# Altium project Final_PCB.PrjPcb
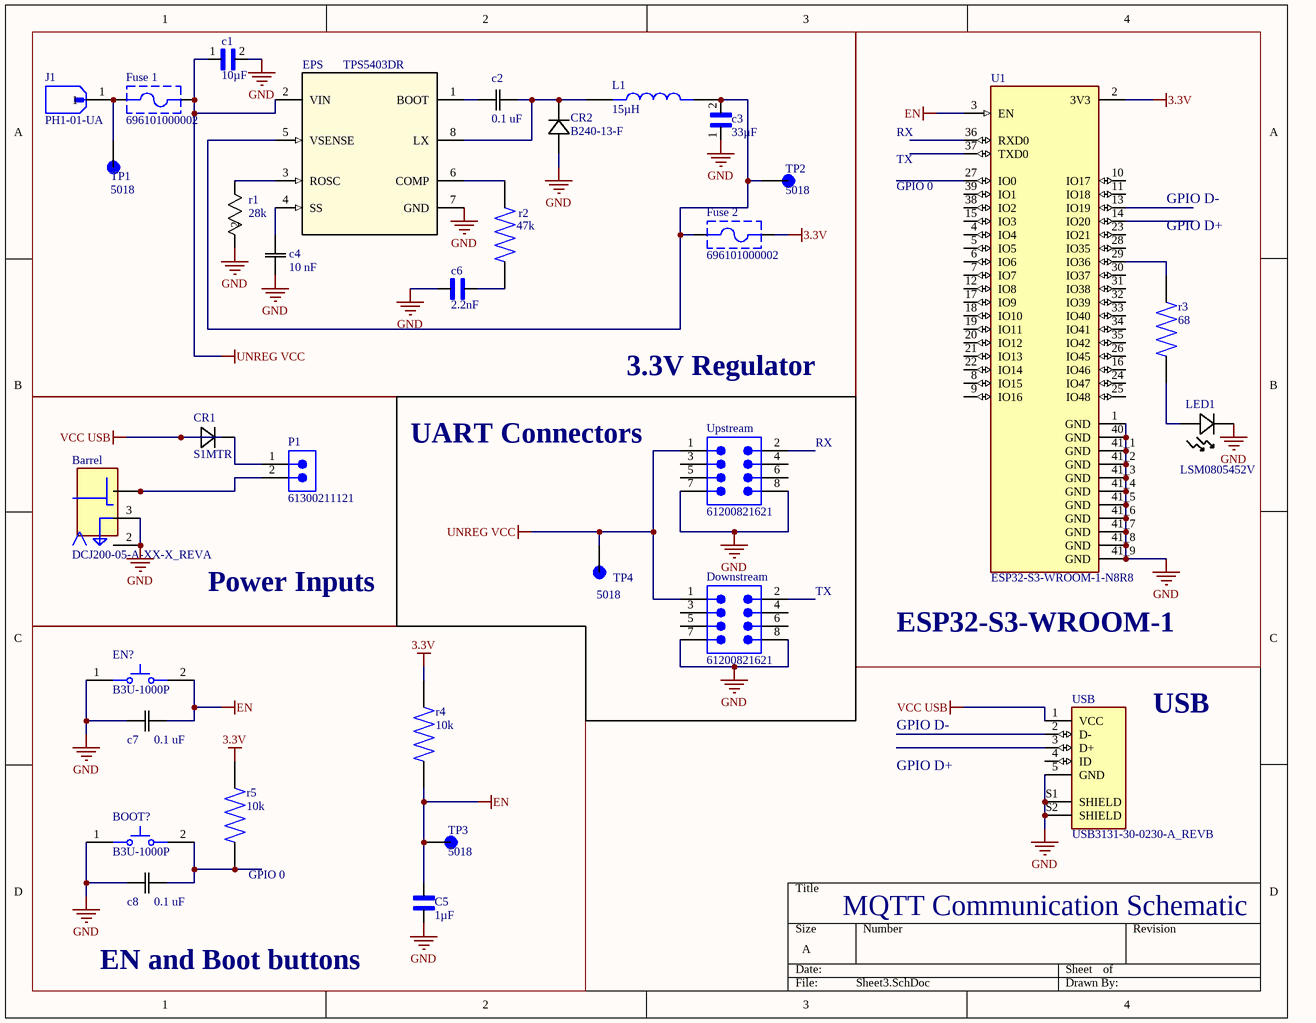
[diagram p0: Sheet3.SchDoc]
1 sheet, 33 parts. Net scope: global (net labels, ports and power ports of the same name join across sheets).
Board file: PCB3.PcbDoc

## Sheet Sheet3.SchDoc
size A; SheetNumber: 1; SheetTotal: 1

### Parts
Barrel  DCJ200-05-A-XX-X_REVA  [GCT_DCJ200-05-A-XX-X_REVA]
BOOT?  B3U-1000P  [OMRON-B3U-1000_V]
c1  value 10µF  [CAPC3216X190N]  (hidden comment: GRJ31CR61E106KE11L)
c2  0.1 uF  [CAP_KGM21_KAV]
c3  value 33µF  [CAPC3216X180N]  (hidden comment: C3216X7S0J336M160AC)
c4  10 nF  [CAP_X7R_0805_AVX]
C5  value 1µF  [CAPC2012X140N]  (hidden comment: CL21B105KBFNNNE)
c6  value 2.2nF  [CAPC3216X130N]  (hidden comment: C3216C0G2J222J115AA)
c7  0.1 uF  [CAP_KGM21_KAV]
c8  0.1 uF  [CAP_KGM21_KAV]
CR1  S1MTR  [SMA_SDS]
CR2  B240-13-F  [SMB_DIO]
Downstream  61200821621  [61200821621]
EN?  B3U-1000P  [OMRON-B3U-1000_V]
EPS  TPS5403DR  [D0008A_N]
Fuse_1  696101000002  [696101000002]
Fuse_2  696101000002  [696101000002]
J1  PH1-01-UA  [ADAM-TECH_PH1-01-UA]
L1  value 15µH  [INDC2012X145N]  (hidden comment: MLF2012C820MT000)
LED1  LSM0805452V  [LED_05452V_VCC]
P1  61300211121  [61300211121]
r1  28k  [RC1206N_YAG]
r2  value 47k  [RESC3116X65N]  (hidden comment: RC1206FR-1047KL)
r3  value 68  [RESC3216X55N]  (hidden comment: HRG3216P-68R0-D-T1)
r4  value 10k  [RESC2012X65N]  (hidden comment: RMCF0805FT10K0)
r5  value 10k  [RESC2012X65N]  (hidden comment: RMCF0805FT10K0)
TP1  5018  [TP470X343]
TP2  5018  [TP470X343]
TP3  5018  [TP470X343]
TP4  5018  [TP470X343]
U1  ESP32-S3-WROOM-1-N8R8  [XCVR_ESP32S3WROOM1N8R8]
Upstream  61200821621  [61200821621]
USB  USB3131-30-0230-A_REVB  [GCT_USB3131-30-0230-A_REVB]

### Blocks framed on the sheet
3.3V Regulator: c1-c4 c6 CR2 EPS Fuse_1 Fuse_2 J1 L1 r1 r2 TP1 TP2
ESP32-S3-WROOM-1: LED1 r3 U1
Power Inputs: Barrel CR1 P1
EN and Boot buttons: BOOT? C5 c7 c8 EN? r4 r5 TP3

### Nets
3.3V: Fuse_2.2 r4.2 r5.2 U1.2(3V3)
EN: C5.1 c7.2 EN?.2 r4.1 TP3.TP U1.3(EN)
GND: Barrel.2 Barrel.3 BOOT?.1 c1.2 c3.1 c4.1 C5.2 c6.1 c7.1 c8.1 CR2.2 Downstream.7 Downstream.8 EN?.1 EPS.7(GND) LED1.2 r1.2 U1.1(GND) U1.40(GND) U1.41_1(GND) U1.41_2(GND) U1.41_3(GND) U1.41_4(GND) U1.41_5(GND) U1.41_6(GND) U1.41_7(GND) U1.41_8(GND) U1.41_9(GND) Upstream.7 Upstream.8 USB.5(GND) USB.S1(SHIELD) USB.S2(SHIELD)
UNREG VCC: c1.1 Downstream.1 EPS.2(VIN) Fuse_1.2 TP4.TP Upstream.1
VCC USB: CR1.2 USB.1(VCC)
NetBarrel_1.1: Barrel.1.1 Barrel.1.2 P1.2
NetBOOT?_2: BOOT?.2 c8.2 r5.1
Netc2_1: c2.1 EPS.1(BOOT)
Netc2_2: c2.2 CR2.1 EPS.8(LX) L1.1
Netc3_2: c3.2 EPS.5(VSENSE) Fuse_2.1 L1.2 TP2.TP
Netc4_2: c4.2 EPS.4(SS)
Netc6_2: c6.2 r2.1
NetCR1_1: CR1.1 P1.1
NetEPS_3: EPS.3(ROSC) r1.1
NetEPS_6: EPS.6(COMP) r2.2
NetFuse_1_1: Fuse_1.1 J1.1 TP1.TP
NetLED1_1: LED1.1 r3.1
Netr3_2: r3.2 U1.29(IO36)

Not connected (* = marked no-connect by the designer): Downstream 2 3 4 5 6; U1 4(IO4) 5(IO5) 6(IO6) 7(IO7) 8(IO15) 9(IO16) 10(IO17) 11(IO18) 12(IO8) 13(IO19) 14(IO20) 15(IO3) 16(IO46) 17(IO9) 18(IO10) 19(IO11) 20(IO12) 21(IO13) 22(IO14) 23(IO21) 24(IO47) 25(IO48) 26(IO45) 27(IO0) 28(IO35) 30(IO37) 31(IO38) 32(IO39) 33(IO40) 34(IO41) 35(IO42) 36(RXD0) 37(TXD0) 38(IO2) 39(IO1); Upstream 2 3 4 5 6; USB 2(D-) 3(D+) 4(ID)

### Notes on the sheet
- RX
- TX
- GPIO 0
- GPIO D+
- GPIO D-
- UART Connectors
- USB
- (near r5) GPIO 0
- MQTT Communication Schematic

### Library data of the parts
Barrel = CMP-002-00092-1: Power Barrel Connector Jack 2.05mm ID (0.081), 5.50mm OD (0.217) Surface Mount, Right Angle; MF: Global Connector Technology; MP: DCJ200-05-A-K1-A
BOOT? EN? = CMP-011-00000-2: Tactile Switch, SPST-NO, 0.05 A, 12 V, -25 to 70 degC, 2-Pin SMD, RoHS, Tape and Reel; Manufacturer: Omron Electronic Components; IP Rating: IP40; Current Rating: 50mA; Max Contact Resistance: 100mohm; Operating Force: 153gf; Throw Configuration: SPST; Resistance: 0.1Ohm; Max Voltage Rating (DC): 12V
c1 = CMP-001-00086-1: CAP CER 10UF 25V X5R 1206
c2 c7 c8 = CMP-001-00087-1: No Description Available; Mfr_Name: KYOCERA AVX; Type: Ceramic Capacitors
c3 = CMP-001-00088-1: 33 ÂµF Â±20% 6.3V Ceramic Capacitor X7S 1206 (3216 Metric); MF: TDK
c4 = CMP-001-00083-1: No Description Available; Mfr_Name: KYOCERA AVX
C5 = CMP-001-00089-1: 1 ÂµF Â±10% 50V Ceramic Capacitor X7R 0805 (2012 Metric); MF: Samsung Electro-Mechanics
c6 = CMP-001-00085-1: 2200 pF Â±5% 630V Ceramic Capacitor C0G, NP0 1206 (3216 Metric); MF: TDK
CR1 = CMP-084-000000-1: No Description Available; Mfr_Name: SMC Diode Solutions
CR2 = CMP-047-000000-1: No Description Available; Mfr_Name: Diodes Inc
Downstream Upstream = CMP-002-00099-1: WR-BHD Male Box Header, THT Straight, pitch 2.54mm, 2 row, 8 pin; Manufacturer: Wurth Elektronik; Working Voltage: 250V; Insulation Resistance: 1000MOhm; Contact Resistance: 20mOhm; Rated Current: 3A; Withstanding Voltage: 500V
EPS = CMP-011-000000-1: No Description Available; Mfr_Name: Texas Instruments
Fuse_1 Fuse_2 = CMP-040-000000-1: WR-FSH Fuseholder THT Blocks PCB Clip Cover; Manufacturer: Wurth Elektronik; Fuse Size: 5x20mm
J1 = CMP-002-00312-1: Pin Header 1P .100 Pitch Plug; MF: Adam Tech
L1 = CMP-006-00021-1: 27 NH 3% LQW1005A27NH00; MF: {'manufacturer': u'TDK Corporation'}
LED1 = CMP-007-00036-1: No Description Available; Mfr_Name: VCC
P1 = CMP-002-00446-1: WR-PHD Pin Header, THT, Vertical, pitch 2.54mm, 1 Row, 2P; Manufacturer: Wurth Elektronik; Working Voltage: 250V; Rated Current: 3A; Contact Resistance: 20mOhm; Withstanding Voltage: 500V
r1 = CMP-009-00179-1: No Description Available; Mfr_Name: Yageo
r2 = CMP-009-00180-1: MF: {'manufacturer': u'YAGEO'}
r3 = CMP-009-00182-1: RES SMD 68 OHM 0.5% 1W 1206; MF: Susumu
r4 r5 = CMP-009-00181-1: MF: {'manufacturer': u'Stackpole Electronics Inc'}
TP1-TP4 = CMP-013-000000-1
U1 = CMP-005-000000-1: Bluetooth, WiFi 802.11b/g/n, Bluetooth v5.0 Transceiver Module 2.4GHz PCB Trace Surface Mount; MF: Espressif Systems
USB = CMP-002-00073-1: USB - micro B USB 2.0 Receptacle Connector 5 Position Through Hole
